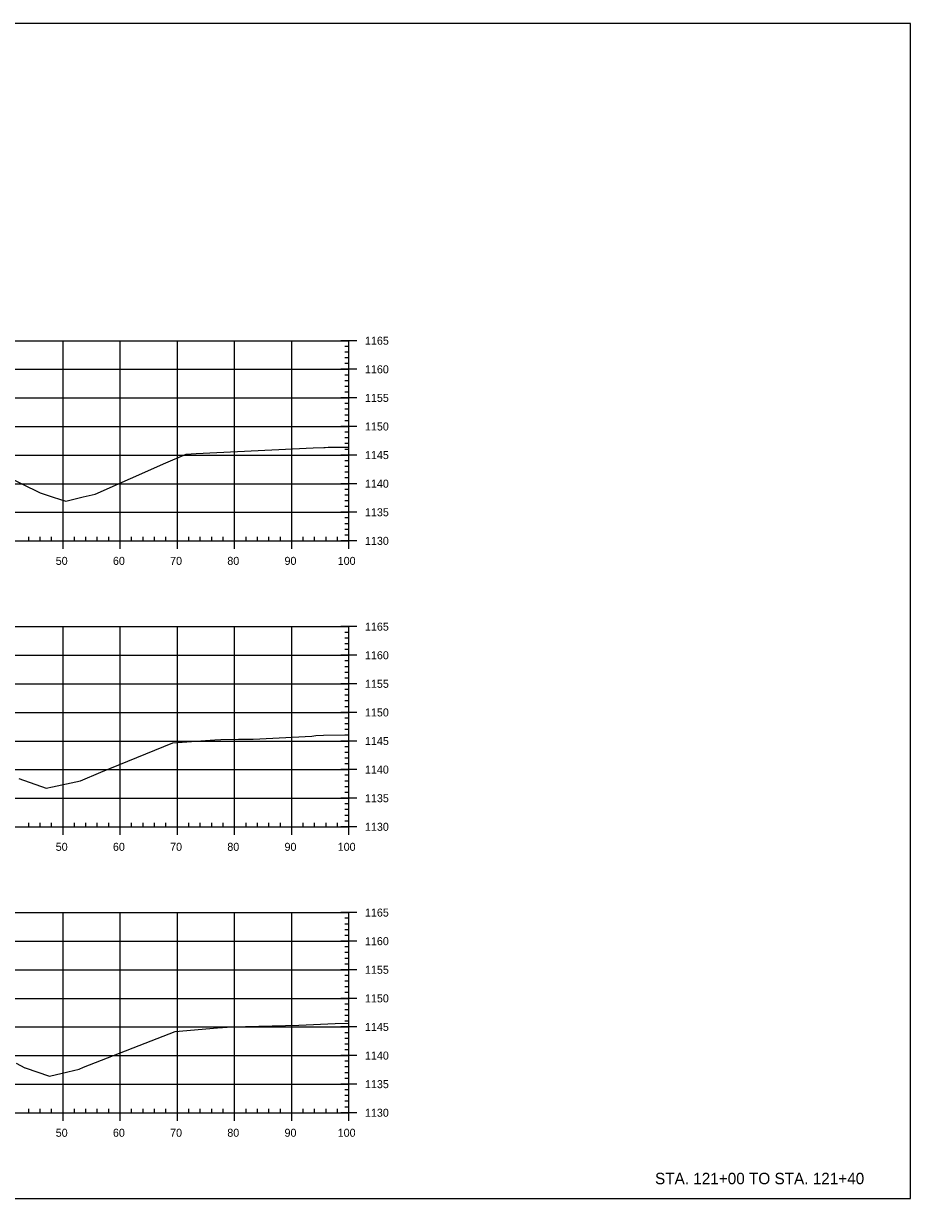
# Model space of a CAD drawing. Extents: x 688474 to 694748, y 765018 to 767373.
# Drawn here: x 690199.4 to 690354.5, y 765017.9 to 765223.3 of the extents above; entities that cross this region are included whole.
import ezdxf

# ---------------------------------------------------------------- set-up
doc = ezdxf.new("R2010")
doc.units = 0
for name, color, linetype in [('60', 7, 'Continuous'), ('R_Exist Surface', 7, 'Continuous'), ('R_Grid', 7, 'Continuous'), ('R_No Plot', 7, 'Continuous')]:
    doc.layers.add(name, color=color, linetype=linetype)

msp = doc.modelspace()

# ---------------------------------------------------------------- linework, layer by layer
at = {"layer": '60'}
for p, q in [((690257.71, 765167.86), (690254.91, 765167.86)), ((690256.31, 765166.86), (690255.61, 765166.86)), ((690256.31, 765132.86), (690256.31, 765167.86)), ((690256.31, 765165.86), (690255.61, 765165.86)), ((690256.31, 765164.86), (690255.61, 765164.86)), ((690256.31, 765163.86), (690255.61, 765163.86)), ((690257.71, 765162.86), (690254.91, 765162.86)), ((690256.31, 765161.86), (690255.61, 765161.86)), ((690256.31, 765160.86), (690255.61, 765160.86)), ((690256.31, 765159.86), (690255.61, 765159.86)), ((690257.71, 765157.86), (690254.91, 765157.86)), ((690256.31, 765158.86), (690255.61, 765158.86)), ((690256.31, 765156.86), (690255.61, 765156.86)), ((690256.31, 765155.86), (690255.61, 765155.86)), ((690256.31, 765154.86), (690255.61, 765154.86)), ((690256.31, 765153.86), (690255.61, 765153.86)), ((690257.71, 765152.86), (690254.91, 765152.86)), ((690256.31, 765151.86), (690255.61, 765151.86)), ((690256.31, 765150.86), (690255.61, 765150.86)), ((690256.31, 765149.86), (690255.61, 765149.86)), ((690257.71, 765147.86), (690254.91, 765147.86)), ((690256.31, 765148.86), (690255.61, 765148.86)), ((690256.31, 765146.86), (690255.61, 765146.86)), ((690256.31, 765145.86), (690255.61, 765145.86)), ((690256.31, 765144.86), (690255.61, 765144.86)), ((690256.31, 765143.86), (690255.61, 765143.86)), ((690257.71, 765142.86), (690254.91, 765142.86)), ((690256.31, 765141.86), (690255.61, 765141.86)), ((690256.31, 765140.86), (690255.61, 765140.86)), ((690256.31, 765139.86), (690255.61, 765139.86)), ((690257.71, 765137.86), (690254.91, 765137.86)), ((690256.31, 765138.86), (690255.61, 765138.86)), ((690256.31, 765136.86), (690255.61, 765136.86)), ((690256.31, 765135.86), (690255.61, 765135.86)), ((690200.31, 765132.86), (690200.31, 765133.56)), ((690202.31, 765132.86), (690202.31, 765133.56)), ((690204.31, 765132.86), (690204.31, 765133.56)), ((690206.31, 765131.46), (690206.31, 765134.26)), ((690208.31, 765132.86), (690208.31, 765133.56)), ((690210.31, 765132.86), (690210.31, 765133.56)), ((690212.31, 765132.86), (690212.31, 765133.56)), ((690214.31, 765132.86), (690214.31, 765133.56)), ((690216.31, 765131.46), (690216.31, 765134.26)), ((690218.31, 765132.86), (690218.31, 765133.56)), ((690220.31, 765132.86), (690220.31, 765133.56)), ((690222.31, 765132.86), (690222.31, 765133.56)), ((690224.31, 765132.86), (690224.31, 765133.56)), ((690226.31, 765131.46), (690226.31, 765134.26)), ((690228.31, 765132.86), (690228.31, 765133.56)), ((690230.31, 765132.86), (690230.31, 765133.56)), ((690232.31, 765132.86), (690232.31, 765133.56)), ((690234.31, 765132.86), (690234.31, 765133.56)), ((690236.31, 765131.46), (690236.31, 765134.26)), ((690238.31, 765132.86), (690238.31, 765133.56)), ((690240.31, 765132.86), (690240.31, 765133.56)), ((690242.31, 765132.86), (690242.31, 765133.56)), ((690244.31, 765132.86), (690244.31, 765133.56)), ((690246.31, 765131.46), (690246.31, 765134.26)), ((690248.31, 765132.86), (690248.31, 765133.56)), ((690250.31, 765132.86), (690250.31, 765133.56)), ((690252.31, 765132.86), (690252.31, 765133.56)), ((690254.31, 765132.86), (690254.31, 765133.56)), ((690256.31, 765134.86), (690255.61, 765134.86)), ((690256.31, 765133.86), (690255.61, 765133.86)), ((690256.31, 765131.46), (690256.31, 765134.26)), ((690056.31, 765132.86), (690256.31, 765132.86)), ((690257.71, 765132.86), (690254.91, 765132.86)), ((690257.71, 765117.86), (690254.91, 765117.86)), ((690256.31, 765116.86), (690255.61, 765116.86)), ((690256.31, 765082.86), (690256.31, 765117.86)), ((690256.31, 765115.86), (690255.61, 765115.86)), ((690256.31, 765114.86), (690255.61, 765114.86)), ((690257.71, 765112.86), (690254.91, 765112.86)), ((690256.31, 765113.86), (690255.61, 765113.86)), ((690256.31, 765111.86), (690255.61, 765111.86)), ((690256.31, 765110.86), (690255.61, 765110.86)), ((690256.31, 765109.86), (690255.61, 765109.86)), ((690256.31, 765108.86), (690255.61, 765108.86)), ((690257.71, 765107.86), (690254.91, 765107.86)), ((690256.31, 765106.86), (690255.61, 765106.86)), ((690256.31, 765105.86), (690255.61, 765105.86)), ((690256.31, 765104.86), (690255.61, 765104.86)), ((690257.71, 765102.86), (690254.91, 765102.86)), ((690256.31, 765103.86), (690255.61, 765103.86)), ((690256.31, 765101.86), (690255.61, 765101.86)), ((690256.31, 765100.86), (690255.61, 765100.86)), ((690256.31, 765099.86), (690255.61, 765099.86)), ((690256.31, 765098.86), (690255.61, 765098.86)), ((690257.71, 765097.86), (690254.91, 765097.86)), ((690256.31, 765096.86), (690255.61, 765096.86)), ((690256.31, 765095.86), (690255.61, 765095.86)), ((690256.31, 765094.86), (690255.61, 765094.86)), ((690257.71, 765092.86), (690254.91, 765092.86)), ((690256.31, 765093.86), (690255.61, 765093.86)), ((690256.31, 765091.86), (690255.61, 765091.86)), ((690256.31, 765090.86), (690255.61, 765090.86)), ((690257.71, 765087.86), (690254.91, 765087.86)), ((690256.31, 765089.86), (690255.61, 765089.86)), ((690256.31, 765088.86), (690255.61, 765088.86)), ((690256.31, 765086.86), (690255.61, 765086.86)), ((690256.31, 765085.86), (690255.61, 765085.86)), ((690206.31, 765081.46), (690206.31, 765084.26)), ((690216.31, 765081.46), (690216.31, 765084.26)), ((690226.31, 765081.46), (690226.31, 765084.26)), ((690236.31, 765081.46), (690236.31, 765084.26)), ((690246.31, 765081.46), (690246.31, 765084.26)), ((690256.31, 765084.86), (690255.61, 765084.86)), ((690256.31, 765083.86), (690255.61, 765083.86)), ((690256.31, 765081.46), (690256.31, 765084.26)), ((690056.31, 765082.86), (690256.31, 765082.86)), ((690200.31, 765082.86), (690200.31, 765083.56)), ((690202.31, 765082.86), (690202.31, 765083.56)), ((690204.31, 765082.86), (690204.31, 765083.56)), ((690208.31, 765082.86), (690208.31, 765083.56)), ((690210.31, 765082.86), (690210.31, 765083.56)), ((690212.31, 765082.86), (690212.31, 765083.56)), ((690214.31, 765082.86), (690214.31, 765083.56)), ((690218.31, 765082.86), (690218.31, 765083.56)), ((690220.31, 765082.86), (690220.31, 765083.56)), ((690222.31, 765082.86), (690222.31, 765083.56)), ((690224.31, 765082.86), (690224.31, 765083.56)), ((690228.31, 765082.86), (690228.31, 765083.56)), ((690230.31, 765082.86), (690230.31, 765083.56)), ((690232.31, 765082.86), (690232.31, 765083.56)), ((690234.31, 765082.86), (690234.31, 765083.56)), ((690238.31, 765082.86), (690238.31, 765083.56)), ((690240.31, 765082.86), (690240.31, 765083.56)), ((690242.31, 765082.86), (690242.31, 765083.56)), ((690244.31, 765082.86), (690244.31, 765083.56)), ((690248.31, 765082.86), (690248.31, 765083.56)), ((690250.31, 765082.86), (690250.31, 765083.56)), ((690252.31, 765082.86), (690252.31, 765083.56)), ((690254.31, 765082.86), (690254.31, 765083.56)), ((690257.71, 765082.86), (690254.91, 765082.86)), ((690257.71, 765067.86), (690254.91, 765067.86)), ((690256.31, 765032.86), (690256.31, 765067.86)), ((690256.31, 765066.86), (690255.61, 765066.86)), ((690256.31, 765065.86), (690255.61, 765065.86)), ((690256.31, 765064.86), (690255.61, 765064.86)), ((690256.31, 765063.86), (690255.61, 765063.86)), ((690257.71, 765062.86), (690254.91, 765062.86)), ((690256.31, 765061.86), (690255.61, 765061.86)), ((690256.31, 765060.86), (690255.61, 765060.86)), ((690256.31, 765059.86), (690255.61, 765059.86)), ((690257.71, 765057.86), (690254.91, 765057.86)), ((690256.31, 765058.86), (690255.61, 765058.86)), ((690256.31, 765056.86), (690255.61, 765056.86)), ((690256.31, 765055.86), (690255.61, 765055.86)), ((690256.31, 765054.86), (690255.61, 765054.86)), ((690256.31, 765053.86), (690255.61, 765053.86)), ((690257.71, 765052.86), (690254.91, 765052.86)), ((690256.31, 765051.86), (690255.61, 765051.86)), ((690256.31, 765050.86), (690255.61, 765050.86)), ((690256.31, 765049.86), (690255.61, 765049.86)), ((690256.31, 765048.86), (690255.61, 765048.86)), ((690257.71, 765047.86), (690254.91, 765047.86)), ((690256.31, 765046.86), (690255.61, 765046.86)), ((690256.31, 765045.86), (690255.61, 765045.86)), ((690256.31, 765044.86), (690255.61, 765044.86)), ((690257.71, 765042.86), (690254.91, 765042.86)), ((690256.31, 765043.86), (690255.61, 765043.86)), ((690256.31, 765041.86), (690255.61, 765041.86)), ((690256.31, 765040.86), (690255.61, 765040.86)), ((690256.31, 765039.86), (690255.61, 765039.86)), ((690256.31, 765038.86), (690255.61, 765038.86)), ((690257.71, 765037.86), (690254.91, 765037.86)), ((690256.31, 765036.86), (690255.61, 765036.86)), ((690256.31, 765035.86), (690255.61, 765035.86)), ((690256.31, 765034.86), (690255.61, 765034.86)), ((690056.31, 765032.86), (690256.31, 765032.86)), ((690200.31, 765032.86), (690200.31, 765033.56)), ((690202.31, 765032.86), (690202.31, 765033.56)), ((690204.31, 765032.86), (690204.31, 765033.56)), ((690206.31, 765031.46), (690206.31, 765034.26)), ((690208.31, 765032.86), (690208.31, 765033.56)), ((690210.31, 765032.86), (690210.31, 765033.56)), ((690212.31, 765032.86), (690212.31, 765033.56)), ((690214.31, 765032.86), (690214.31, 765033.56)), ((690216.31, 765031.46), (690216.31, 765034.26)), ((690218.31, 765032.86), (690218.31, 765033.56)), ((690220.31, 765032.86), (690220.31, 765033.56)), ((690222.31, 765032.86), (690222.31, 765033.56)), ((690224.31, 765032.86), (690224.31, 765033.56)), ((690226.31, 765031.46), (690226.31, 765034.26)), ((690228.31, 765032.86), (690228.31, 765033.56)), ((690230.31, 765032.86), (690230.31, 765033.56)), ((690232.31, 765032.86), (690232.31, 765033.56)), ((690234.31, 765032.86), (690234.31, 765033.56)), ((690236.31, 765031.46), (690236.31, 765034.26)), ((690238.31, 765032.86), (690238.31, 765033.56)), ((690240.31, 765032.86), (690240.31, 765033.56)), ((690242.31, 765032.86), (690242.31, 765033.56)), ((690244.31, 765032.86), (690244.31, 765033.56)), ((690246.31, 765031.46), (690246.31, 765034.26)), ((690248.31, 765032.86), (690248.31, 765033.56)), ((690250.31, 765032.86), (690250.31, 765033.56)), ((690252.31, 765032.86), (690252.31, 765033.56)), ((690254.31, 765032.86), (690254.31, 765033.56)), ((690257.71, 765032.86), (690254.91, 765032.86)), ((690256.31, 765033.86), (690255.61, 765033.86)), ((690256.31, 765031.46), (690256.31, 765034.26))]:
    msp.add_line(p, q, dxfattribs=at)
at = {"layer": 'R_Exist Surface'}
for points in [[(690189.8, 765147.38), (690202.31, 765141.25), (690204.57, 765140.49), (690206.81, 765139.8), (690209.81, 765140.55), (690211.93, 765141.04), (690224.26, 765146.49), (690227.84, 765148.01), (690229.59, 765148.13), (690250.03, 765149.11), (690251.89, 765149.2), (690252.14, 765149.21), (690252.67, 765149.22), (690256.31, 765149.27)], [(690198.57, 765091.31), (690203.36, 765089.6), (690204.45, 765089.85), (690209.35, 765090.88), (690212.93, 765092.4), (690225.52, 765097.57), (690232.83, 765098.07), (690233.89, 765098.15), (690237, 765098.16), (690239.57, 765098.2), (690249.83, 765098.72), (690250.16, 765098.78), (690250.54, 765098.85), (690251.84, 765098.87), (690256.31, 765098.96)], [(690198.1, 765041.55), (690199.62, 765040.73), (690199.72, 765040.69), (690203.93, 765039.27), (690207.18, 765040.04), (690209.12, 765040.5), (690209.88, 765040.82), (690225.91, 765047.05), (690233.33, 765047.73), (690235.88, 765047.91), (690247.56, 765048.19), (690253.91, 765048.44), (690256.31, 765048.5)]]:
    msp.add_lwpolyline(points, dxfattribs=at)
at = {"layer": 'R_Grid'}
for p, q in [((690056.31, 765167.86), (690256.31, 765167.86)), ((690206.31, 765132.86), (690206.31, 765167.86)), ((690216.31, 765132.86), (690216.31, 765167.86)), ((690226.31, 765132.86), (690226.31, 765167.86)), ((690236.31, 765132.86), (690236.31, 765167.86)), ((690246.31, 765132.86), (690246.31, 765167.86)), ((690256.31, 765132.86), (690256.31, 765167.86)), ((690056.31, 765162.86), (690256.31, 765162.86)), ((690056.31, 765157.86), (690256.31, 765157.86)), ((690056.31, 765152.86), (690256.31, 765152.86)), ((690056.31, 765147.86), (690256.31, 765147.86)), ((690056.31, 765142.86), (690256.31, 765142.86)), ((690056.31, 765137.86), (690256.31, 765137.86)), ((690056.31, 765132.86), (690256.31, 765132.86)), ((690056.31, 765117.86), (690256.31, 765117.86)), ((690206.31, 765082.86), (690206.31, 765117.86)), ((690216.31, 765082.86), (690216.31, 765117.86)), ((690226.31, 765082.86), (690226.31, 765117.86)), ((690236.31, 765082.86), (690236.31, 765117.86)), ((690246.31, 765082.86), (690246.31, 765117.86)), ((690256.31, 765082.86), (690256.31, 765117.86)), ((690056.31, 765112.86), (690256.31, 765112.86)), ((690056.31, 765107.86), (690256.31, 765107.86)), ((690056.31, 765102.86), (690256.31, 765102.86)), ((690056.31, 765097.86), (690256.31, 765097.86)), ((690056.31, 765092.86), (690256.31, 765092.86)), ((690056.31, 765087.86), (690256.31, 765087.86)), ((690056.31, 765082.86), (690256.31, 765082.86)), ((690056.31, 765067.86), (690256.31, 765067.86)), ((690206.31, 765032.86), (690206.31, 765067.86)), ((690216.31, 765032.86), (690216.31, 765067.86)), ((690226.31, 765032.86), (690226.31, 765067.86)), ((690236.31, 765032.86), (690236.31, 765067.86)), ((690246.31, 765032.86), (690246.31, 765067.86)), ((690256.31, 765032.86), (690256.31, 765067.86)), ((690056.31, 765062.86), (690256.31, 765062.86)), ((690056.31, 765057.86), (690256.31, 765057.86)), ((690056.31, 765052.86), (690256.31, 765052.86)), ((690056.31, 765047.86), (690256.31, 765047.86)), ((690056.31, 765042.86), (690256.31, 765042.86)), ((690056.31, 765037.86), (690256.31, 765037.86)), ((690056.31, 765032.86), (690256.31, 765032.86))]:
    msp.add_line(p, q, dxfattribs=at)
at = {"layer": 'R_No Plot'}
msp.add_lwpolyline([(690038.31, 765017.86), (690354.49, 765017.86), (690354.49, 765223.32), (690038.31, 765223.32)], close=True, dxfattribs=at)

# ---------------------------------------------------------------- texts
at = {"layer": '60'}
for s, height, p in [('1165', 1.4, (690259.11, 765167.16)), ('1160', 1.4, (690259.11, 765162.16)), ('1155', 1.4, (690259.11, 765157.16)), ('1150', 1.4, (690259.11, 765152.16)), ('1145', 1.4, (690259.11, 765147.16)), ('1140', 1.4, (690259.11, 765142.16)), ('1135', 1.4, (690259.11, 765137.16)), ('1130', 1.4, (690259.11, 765132.16)), ('50', 1.4, (690205.04, 765128.66)), ('60', 1.4, (690215.04, 765128.66)), ('70', 1.4, (690225.04, 765128.66)), ('80', 1.4, (690235.04, 765128.66)), ('90', 1.4, (690245.04, 765128.66)), ('100', 1.4, (690254.34, 765128.66)), ('1165', 1.4, (690259.11, 765117.16)), ('1160', 1.4, (690259.11, 765112.16)), ('1155', 1.4, (690259.11, 765107.16)), ('1150', 1.4, (690259.11, 765102.16)), ('1145', 1.4, (690259.11, 765097.16)), ('1140', 1.4, (690259.11, 765092.16)), ('1135', 1.4, (690259.11, 765087.16)), ('1130', 1.4, (690259.11, 765082.16)), ('50', 1.4, (690205.04, 765078.66)), ('60', 1.4, (690215.04, 765078.66)), ('70', 1.4, (690225.04, 765078.66)), ('80', 1.4, (690235.04, 765078.66)), ('90', 1.4, (690245.04, 765078.66)), ('100', 1.4, (690254.34, 765078.66)), ('1165', 1.4, (690259.11, 765067.16)), ('1160', 1.4, (690259.11, 765062.16)), ('1155', 1.4, (690259.11, 765057.16)), ('1150', 1.4, (690259.11, 765052.16)), ('1145', 1.4, (690259.11, 765047.16)), ('1140', 1.4, (690259.11, 765042.16)), ('1135', 1.4, (690259.11, 765037.16)), ('1130', 1.4, (690259.11, 765032.16)), ('50', 1.4, (690205.04, 765028.66)), ('60', 1.4, (690215.04, 765028.66)), ('70', 1.4, (690225.04, 765028.66)), ('80', 1.4, (690235.04, 765028.66)), ('90', 1.4, (690245.04, 765028.66)), ('100', 1.4, (690254.34, 765028.66)), ('STA. 121+00 TO STA. 121+40', 2, (690309.82, 765020.36))]:
    msp.add_text(s, height=height, dxfattribs=at).set_placement(p)

doc.saveas('drawing.dxf')
